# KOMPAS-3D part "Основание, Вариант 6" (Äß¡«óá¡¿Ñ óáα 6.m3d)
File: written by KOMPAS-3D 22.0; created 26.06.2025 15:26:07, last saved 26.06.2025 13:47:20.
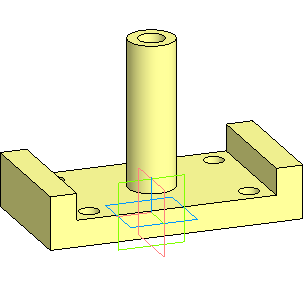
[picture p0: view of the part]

Document properties: Автор: Helen; Полное имя файла: D:\MY\WORK\MPEI\ППЭ_2025-2026\Варианты\Вар 6 СБ\Основание вар 6.m3d

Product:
- Part/product: Основание  | designation Вариант 6
    Масса: 4.013273

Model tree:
1. Эскиз:1
2. Элемент выдавливания:1
     Расстояние 1 = 20
3. Эскиз:3  (with: Элемент выдавливания:1)
4. Элемент выдавливания:3
     Расстояние 2 = 20
5. Массив по сетке:1  (with: Элемент выдавливания:3, Эскиз:3, Элемент выдавливания:1)  (4 pattern instances)
     Шаг 1 = 120; Угол раствора = 90; Шаг 2 = 70
6. Эскиз:4  (with: Элемент выдавливания:1)
7. Элемент выдавливания:4
     Расстояние 1 = 110
8. Эскиз:5  (with: Элемент выдавливания:4)
9. Элемент выдавливания:5
     Расстояние 2 = 130
10. Эскиз:6  (with: Элемент выдавливания:1)
11. Элемент выдавливания:6
     Расстояние 1 = 20
12. Зеркальный массив:1
13. Экземпляр ( 1 )
14. Экземпляр ( 2 )  (with: Элемент выдавливания:6)

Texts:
  Вариант 6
